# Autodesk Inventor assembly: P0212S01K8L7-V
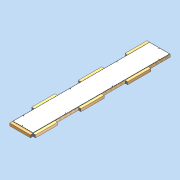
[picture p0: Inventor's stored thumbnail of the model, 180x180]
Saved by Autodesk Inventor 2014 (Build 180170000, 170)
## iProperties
Created: 2011-09
Part Number: P0212S01K8L7-V
Document SubType Name: Assembly
Designer: david.appleford
Description: 0.5w x 3w 01 Panel - 8 Locks 7 Lugs
Mass: 43000 g
Surface Area: 57434.1 cm^2
Volume: 173818 cm^3
Density: 0.247385 g/cm^3
Cost Center: £167.00
Justset: False
Title: 0.5w x 3w 01 Panel - 8 Locks 7 Lugs
Author: david.appleford
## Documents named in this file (5)
- C:\Documents and Settings\john.everitt\Local Settings\My Documents\Vault\Production MkII\VIRTUAL ELEMENTS\Virtual Walls\Virtual Timber + MgO\P0212S01K8L7-V.iam
- C:\Documents and Settings\john.everitt\Local Settings\My Documents\Vault\Production MkII\VIRTUAL ELEMENTS\Virtual Lugs\Superceded Lugs\LA02C3V.ipt
- C:\Documents and Settings\john.everitt\Local Settings\My Documents\Vault\Production MkII\VIRTUAL ELEMENTS\Virtual Lugs\Superceded Lugs\LA02M3V.ipt
- C:\Documents and Settings\john.everitt\Local Settings\My Documents\Vault\Production MkII\VIRTUAL ELEMENTS\Virtual Lugs\Superceded Lugs\LA02E3V.ipt
- C:\Documents and Settings\john.everitt\Local Settings\My Documents\Vault\Production MkII\VIRTUAL ELEMENTS\Virtual Walls\Virtual Timber + MgO\P0212S01K8-V.ipt
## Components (8 placed, 4 different names)
1. P0212S01K8-V:1 — Mate:1, Flush:1, Flush:2, Mate:2, Flush:3, Flush:4, Mate:3, Flush:5, Flush:6, Mate:5, Mate:6, Flush:9, Flush:10, Mate:7, Mate:8, Flush:11, Flush:12
2. LA02C3:1 — Mate:1, Flush:1, Flush:2, Mate:9
3. LA02E3:1 — Mate:2, Flush:3, Flush:4
4. LA02C3:4 — Mate:3, Flush:5, Flush:6, Mate:11
5. LA02M3:1 — Mate:6, Flush:9, Mate:11, Mate:12
6. LA02M3:2 — Mate:5, Flush:10, Mate:12
7. LA02M3:3 — Mate:8, Flush:12, Mate:10
8. LA02M3:4 — Mate:7, Flush:11, Mate:9, Mate:10
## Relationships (21: Mate 11, Flush 10)
- Mate:1: P0212S01K8-V:1 ↔ LA02C3:1
- Flush:1: P0212S01K8-V:1 ↔ LA02C3:1
- Flush:2: P0212S01K8-V:1 ↔ LA02C3:1
- Mate:2: P0212S01K8-V:1 ↔ LA02E3:1
- Flush:3: P0212S01K8-V:1 ↔ LA02E3:1
- Flush:4: P0212S01K8-V:1 ↔ LA02E3:1
- Mate:3: P0212S01K8-V:1 ↔ LA02C3:4
- Flush:5: P0212S01K8-V:1 ↔ LA02C3:4
- Flush:6: P0212S01K8-V:1 ↔ LA02C3:4
- Mate:5: P0212S01K8-V:1 ↔ LA02M3:2
- Mate:6: P0212S01K8-V:1 ↔ LA02M3:1
- Flush:9: P0212S01K8-V:1 ↔ LA02M3:1
- Flush:10: P0212S01K8-V:1 ↔ LA02M3:2
- Mate:7: P0212S01K8-V:1 ↔ LA02M3:4
- Mate:8: P0212S01K8-V:1 ↔ LA02M3:3
- Flush:11: P0212S01K8-V:1 ↔ LA02M3:4
- Flush:12: P0212S01K8-V:1 ↔ LA02M3:3
- Mate:9: LA02C3:1 ↔ LA02M3:4
- Mate:10: LA02M3:3 ↔ LA02M3:4
- Mate:11: LA02C3:4 ↔ LA02M3:1
- Mate:12: LA02M3:1 ↔ LA02M3:2
## Named parameters: t = 1 mm, Cl = 2 mm
